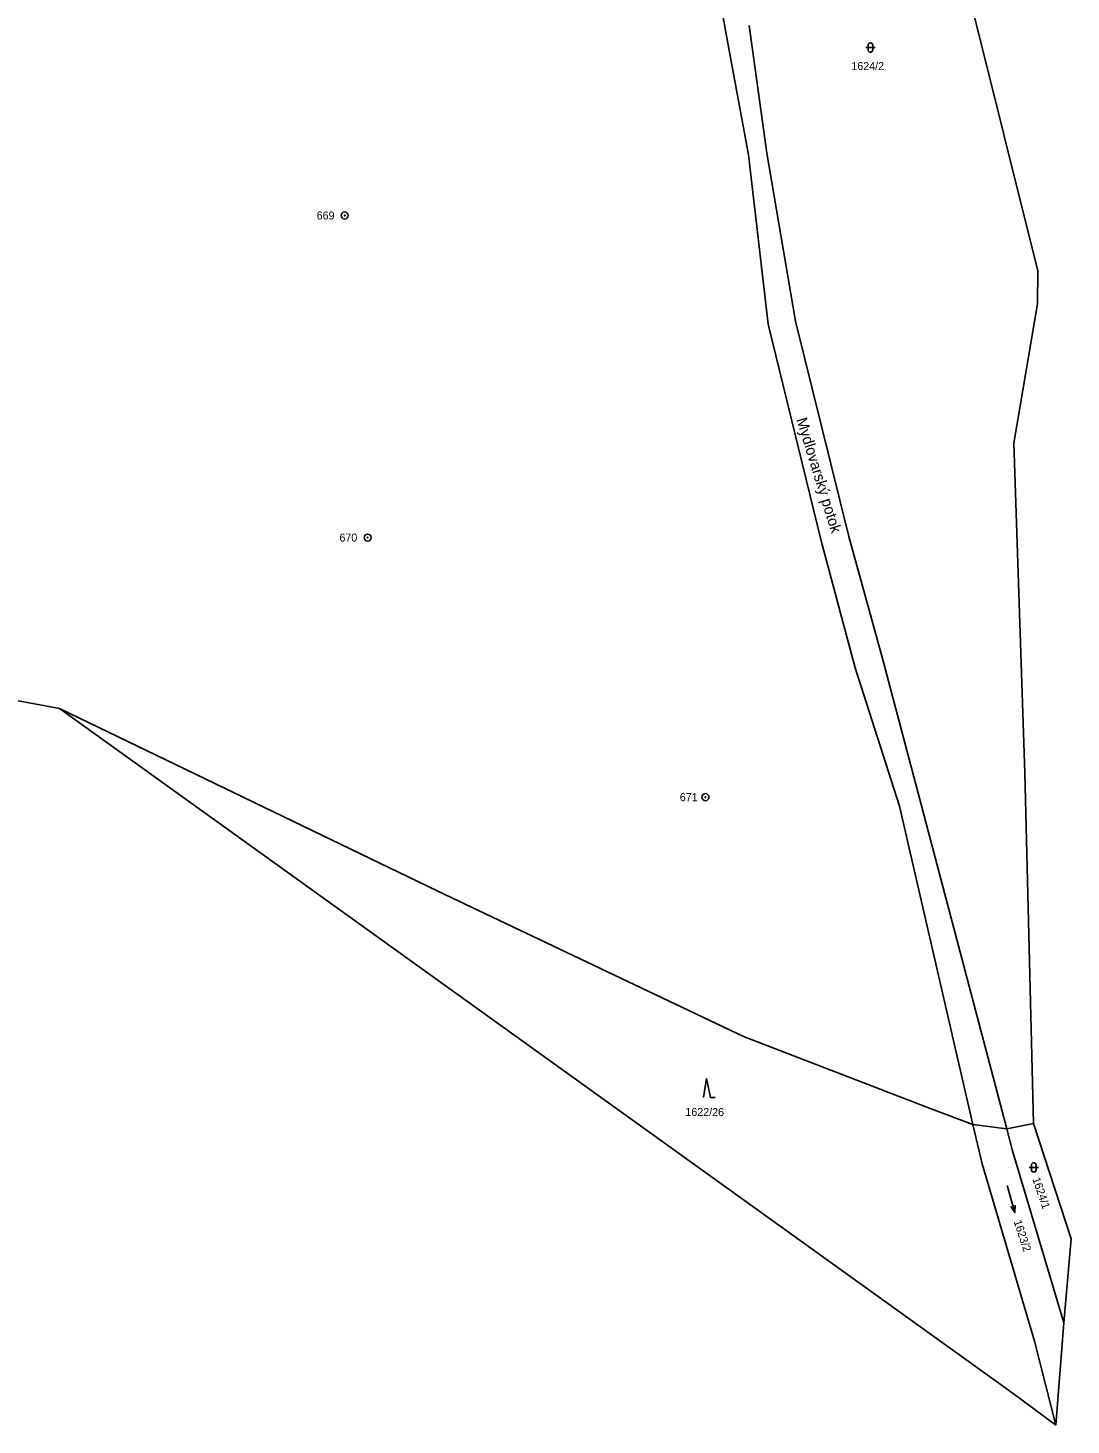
# Model space of a CAD drawing. Extents: x -763296 to -761805, y -1153670 to -1152034.
# Drawn here: x -762026.5 to -761804.9, y -1153669.8 to -1153373 of the extents above; entities that cross this region are included whole.
import ezdxf

# ---------------------------------------------------------------- set-up
doc = ezdxf.new("R2010")
doc.units = 0
for name, color, linetype in [('Vrstva 1', 7, 'Continuous'), ('Vrstva 13', 7, 'Continuous'), ('Vrstva 15', 7, 'Continuous'), ('Vrstva 17', 7, 'Continuous'), ('Vrstva 18', 7, 'Continuous'), ('Vrstva 24', 7, 'Continuous'), ('Vrstva 25', 7, 'Continuous'), ('Vrstva 6', 7, 'Continuous')]:
    doc.layers.add(name, color=color, linetype=linetype)

msp = doc.modelspace()

# ---------------------------------------------------------------- linework, layer by layer
at = {"layer": 'Vrstva 1'}
for p, q in [((-761880.86, -1153359.25), (-761878.3, -1153373.52)), ((-761878.3, -1153373.52), (-761873.47, -1153399.93)), ((-761873.29, -1153372.49), (-761869.53, -1153399.64)), ((-761873.47, -1153399.93), (-761869.23, -1153435.93)), ((-761869.53, -1153399.64), (-761863.49, -1153435.31)), ((-761869.23, -1153435.93), (-761857.93, -1153482.26)), ((-761852.16, -1153481.05), (-761863.49, -1153435.31)), ((-761844.97, -1153506.96), (-761852.16, -1153481.05)), ((-761857.93, -1153482.26), (-761850.75, -1153508.95)), ((-761844.97, -1153506.96), (-761836.76, -1153538)), ((-761850.75, -1153508.95), (-761841.35, -1153538.3)), ((-761841.35, -1153538.3), (-761825.77, -1153605.94)), ((-761836.76, -1153538), (-761818.55, -1153606.87)), ((-761825.77, -1153605.94), (-761823.83, -1153614.35)), ((-761818.55, -1153606.87), (-761817.32, -1153611.52)), ((-761817.32, -1153611.52), (-761806.48, -1153648.08)), ((-761823.83, -1153614.35), (-761812.69, -1153651.96)), ((-761812.69, -1153651.96), (-761808.13, -1153669.81))]:
    msp.add_line(p, q, dxfattribs=at)
at = {"layer": 'Vrstva 13'}
for p, q in [((-761832.99, -1153340.46), (-761811.96, -1153424.58)), ((-761812.04, -1153431.59), (-761811.96, -1153424.58)), ((-761817.06, -1153461.22), (-761812.04, -1153431.59)), ((-761814.73, -1153531.26), (-761817.06, -1153461.22)), ((-762084.3, -1153505.79), (-762019.83, -1153517.58)), ((-762019.83, -1153517.58), (-761818.95, -1153661.83)), ((-761812.9, -1153605.72), (-761814.73, -1153531.26)), ((-761804.91, -1153630.24), (-761812.9, -1153605.72)), ((-761806.48, -1153648.08), (-761804.91, -1153630.24)), ((-761808.13, -1153669.81), (-761806.48, -1153648.08)), ((-761818.95, -1153661.83), (-761815.55, -1153664.34)), ((-761815.55, -1153664.34), (-761808.13, -1153669.81))]:
    msp.add_line(p, q, dxfattribs=at)
at = {"layer": 'Vrstva 24'}
for centre, radius in [((-761959.24, -1153412.85), 0.75), ((-761959.24, -1153412.85), 0.1), ((-761954.36, -1153481.28), 0.75), ((-761954.36, -1153481.28), 0.1), ((-761882.59, -1153536.42), 0.75), ((-761882.59, -1153536.42), 0.1)]:
    msp.add_circle(centre, radius, dxfattribs=at)
at = {"layer": 'Vrstva 25'}
for p, q in [((-761848.53, -1153377.17), (-761846.53, -1153377.17)), ((-761848.03, -1153377.67), (-761848.03, -1153376.67)), ((-761847.03, -1153376.67), (-761847.03, -1153377.67)), ((-761813.83, -1153615.07), (-761811.83, -1153615.07)), ((-761813.33, -1153615.57), (-761813.33, -1153614.57)), ((-761812.33, -1153614.57), (-761812.33, -1153615.57))]:
    msp.add_line(p, q, dxfattribs=at)
for points in [[(-761883.04, -1153600.19), (-761882.34, -1153596.19), (-761881.54, -1153600.19), (-761880.54, -1153600.19)], [(-761818.474, -1153618.912), (-761816.846, -1153624.688), (-761816.772, -1153623.108)], [(-761816.846, -1153624.688), (-761817.735, -1153623.379)]]:
    msp.add_lwpolyline(points, dxfattribs=at)
for centre, start, end in [((-761847.53, -1153376.67), 0, 180), ((-761847.53, -1153377.67), 180, 0), ((-761812.83, -1153614.57), 0, 180), ((-761812.83, -1153615.57), 180, 0)]:
    msp.add_arc(centre, 0.5, start, end, dxfattribs=at)
at = {"layer": 'Vrstva 6'}
for p, q in [((-761939.47, -1153556.37), (-762019.83, -1153517.58)), ((-761874.53, -1153587.23), (-761939.47, -1153556.37)), ((-761834.66, -1153602.63), (-761874.53, -1153587.23)), ((-761825.77, -1153605.94), (-761834.66, -1153602.63)), ((-761818.55, -1153606.87), (-761825.77, -1153605.94)), ((-761812.9, -1153605.72), (-761818.55, -1153606.87))]:
    msp.add_line(p, q, dxfattribs=at)

# ---------------------------------------------------------------- texts
at = {"layer": 'Vrstva 15'}
msp.add_text('Mydlovarský potok', height=2.3, rotation=287.16645, dxfattribs=at).set_placement((-761863.31, -1153456.189))
at = {"layer": 'Vrstva 17'}
for s, p in [('669', (-761965.194, -1153413.7)), ('670', (-761960.354, -1153482.13)), ('671', (-761888.036, -1153537.27))]:
    msp.add_text(s, height=1.7, dxfattribs=at).set_placement(p)
at = {"layer": 'Vrstva 18'}
msp.add_text('1624/2', height=1.7, dxfattribs=at).set_placement((-761851.592, -1153381.95))
for s, rotation, p in [('1622/26', 359.53102, (-761886.864, -1153604.122)), ('1624/1', 288.88532, (-761813.163, -1153617.498)), ('1623/2', 288.36966, (-761817.123, -1153626.556))]:
    msp.add_text(s, height=1.7, rotation=rotation, dxfattribs=at).set_placement(p)

doc.saveas('drawing.dxf')
